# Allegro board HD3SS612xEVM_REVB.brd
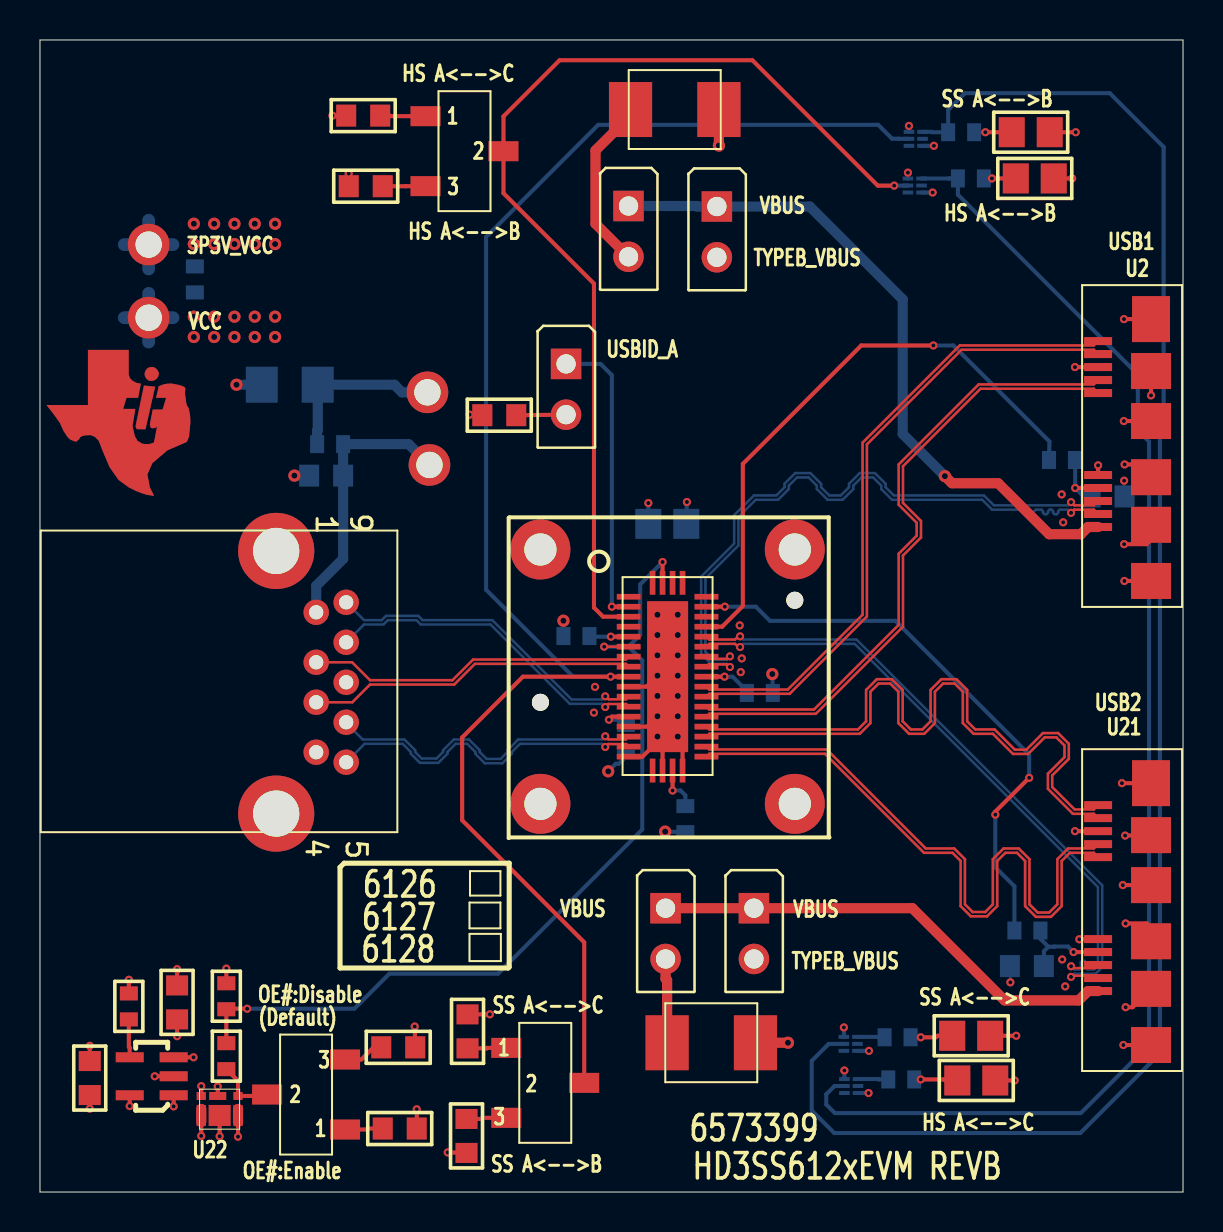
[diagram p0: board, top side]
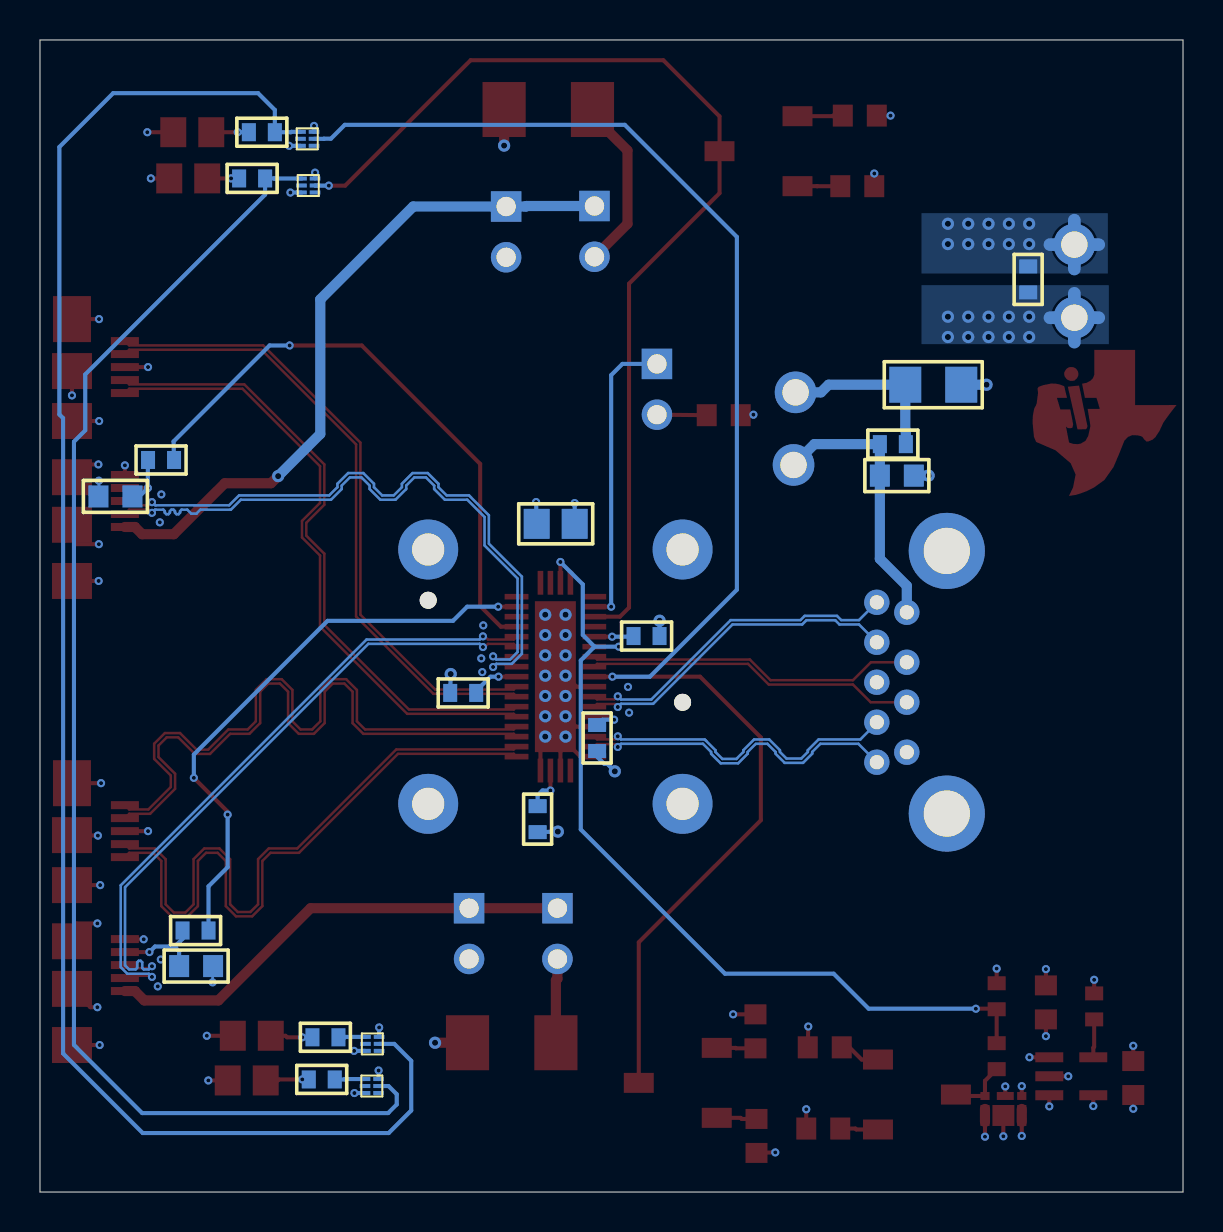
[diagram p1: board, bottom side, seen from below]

Outline 57.18 x 57.63 mm; copper layers: TOP, L2, L3, BOTTOM. Coordinates in mm from the lower left corner of the outline.
Outline path: 0,57.63 0,0 57.18,0 57.18,57.63 0,57.63

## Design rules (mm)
net group DIFFPAIR0: nets DEV_SSA_RX(N) DEV_SSA_RX(P)
net group DIFFPAIR1: nets DEV_HSA_DM DEV_HSA_DP
net group DIFFPAIR2: nets DEV_SSA_TX(N) DEV_SSA_TX(P)
net group DIFFPAIR3: nets USB1_DEV_SSB_RX(N) USB1_DEV_SSB_RX(P)
net group DIFFPAIR4: nets USB1_DEV_SSB_TX(N) USB1_DEV_SSB_TX(P)
net group DIFFPAIR5: nets USB1_HSB_DM USB1_HSB_DP
net group DIFFPAIR6: nets USB2_DEV_SSC_RX(N) USB2_DEV_SSC_RX(P)
net group DIFFPAIR7: nets USB2_DEV_SSC_TX(N) USB2_DEV_SSC_TX(P)
net group DIFFPAIR8: nets USB2_HSC_DM USB2_HSC_DP

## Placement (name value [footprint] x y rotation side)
C1  0.1uF  [0402]  29.31 23.36 270 bottom
C2  0.1uF  [0402]  27.48 27.81 180 bottom
C3  0.1uF  [0402]  32.28 19.3 270 bottom
C4  0.1uF  [0402]  35.36 24.97 0 bottom
C8  NC, 10uF  [0805]  30.43 33.43 0 bottom
C100  NC,100u  [0603]  15.16 35.84 180 bottom
C182  0.01uF  [0402]  4.45 8.64 90 top
C188  1uF  [0603]  6.86 8.64 90 top
C189  1uF  [0603]  2.49 4.85 90 top
D1  SCHOTTKY  [DO-214AA]  31.75 54.15 180 top
D5  SCHOTTKY  [DO-214AA]  33.58 7.47 180 top
D6  LED RED 0805  [0805]  48.61 53.02 0 top
D7  LED RED 0805  [0805]  45.63 7.82 0 top
D8  LED Orange 0805  [0805]  48.81 50.71 0 top
D9  LED Orange 0805  [0805]  45.89 5.58 0 top
F1  Fuse  [1206]  13.89 40.39 180 bottom
J1  CON02  [BERG1X2]  31.29 14.2 0 top
J2  CON02  [BERG1X2]  35.71 14.2 0 top
J3  CON02  [BERG1X2]  29.44 49.33 0 top
J4  CON02  [BERG1X2]  33.86 49.3 0 top
J5  CON02  [BERG1X2]  26.31 41.43 0 top
LP1  LP  [TESTLOOP]  5.44 47.4 0 top
LP2  LP  [TESTLOOP]  5.44 43.74 0 top
LP3  LP  [TESTLOOP]  19.48 36.37 0 top
LP4  LP  [TESTLOOP]  19.38 40.01 0 top
NOREF  -  []  3.54 0 90 top
NOREF#2  -  []  0 2 0 top
NOREF#3  -  []  4.01 39.17 0 top
R1  0R  [0402]  7.75 46.3 270 bottom
R2  4.98 K  [0603]  21.34 1.96 90 top
R3  4.98 K  [0603]  21.39 7.19 90 top
R6  4.98 K  [0603]  18.77 7.24 180 top
R7  4.98 K  [0603]  17.15 3.18 0 top
R18  100K  [0402]  9.32 9.14 90 top
R19  50K  [0402]  9.32 6.15 90 top
R20  0R  [0402]  15.16 37.41 180 bottom
R101  350  [0402]  46.73 53.02 180 bottom
R102  350  [0402]  43.55 7.74 180 bottom
R103  350  [0402]  45.91 50.71 0 bottom
R104  350  [0402]  42.43 5.63 0 bottom
R105  4.98 K  [0603]  15.44 50.32 0 top
R106  4.98 K  [0603]  17.02 53.85 180 top
R109  4.98 K  [0603]  23.83 38.86 180 top
R110  0R  [0402]  50.47 36.62 0 bottom
R111  NC, 4.98 K  [0603]  52.55 34.8 0 bottom
R112  0R  [0402]  48.74 13.08 0 bottom
R113  NC, 4.98 K  [0603]  50.22 11.3 180 bottom
SW1  Switch CJS-1201  [CJS-1200B]  13.31 4.88 180 top
SW2  Switch CJS-1201  [CJS-1200B]  25.27 5.46 0 top
SW3  Switch CJS-1201  [CJS-1200B]  21.23 52.07 0 top
U1  HD3SS612x Mux switch  [IRONWOOD_42PIN_C9856]  31.39 25.78 270 top
U2  USB3.0 Micro-B Receptacle  [USB3_MICRO_B_RECEPTACLE]  52.93 34.57 90 top
U20  USB3_STANDARD_TYPE_A_RECEPTACLE  [USB3_TYPEA]  15.32 25.5 270 top
U21  USB3.0 Micro-B Receptacle  [USB3_MICRO_B_RECEPTACLE]  52.93 11.35 90 top
U22  PMOS_PowerSwitch  [CSD25302Q2]  9.91 6.05 90 top
U23  SN74LVC1G04DSF  [DSF]  43.81 52.69 0 bottom
U24  SN74LVC1G04DSF  [DSF]  40.55 7.41 0 bottom
U25  LP3985IM5-3.3  [DBV_R-PDSO-G5]  5.59 5.79 180 top
U26  SN74LVC1G04DSF  [DSF]  43.76 50.35 0 bottom
U27  SN74LVC1G04DSF  [DSF]  40.58 5.3 0 bottom

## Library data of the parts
C1-C4 C8 = CAP
C100 = PCap_CaseD
C182 C188 C189 = CAP NP
D1 D5 = SCHOTTKY
D6-D9 = DIODE
F1 = Fuse_0
J1-J5 = CON02
LP1-LP4 = TESTLOOP
R1 R20 R110 R112 = R
R2 R3 R6 R7 R105 R106 R109 R111 R113 = r0603
R18 R19 = RES
R101-R104 = R_4
SW1-SW3 = Switch CJS-1201
U1 = HD3SS6126 Mux switch_11
U2 = USB3_1.0 Micro-B Receptacle
U20 = TMP_0
U21 = USB3_2.0 Micro-B Receptacle
U22 = PMOS_PowerSwitch_3
U23 U24 U26 U27 = SN74LVC1G04DSF
U25 = LP3985IM5-3_0.3

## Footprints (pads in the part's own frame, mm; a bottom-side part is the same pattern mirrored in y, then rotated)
0402
  rect 0.7x0.9 smd: 1(0,0) 2(1.3,0)
0603
  rect 1x1.1 smd: 1(0,0) 2(1.7,0)
0805
  rect 1.3x1.5 smd: 1(0,0) 2(1.9,0)
1206
  rect 1.6x1.8 smd: 1(0,0) 2(2.8,0)
BERG1X2
  rect 1.524x1.524 hole 0.965: 1(0,0)
  round 1.524 hole 0.965: 2(0,-2.54)
CJS-1200B
  rect 1.5x1 smd: 1(-1.95,1.75) 2(1.95,0) 3(-1.95,-1.75)
CSD25302Q2
  rect 0.4x0.46 smd: 1(-2.54,0) 2(-1.89,0) 3(-1.24,0) 4(-1.24,1.84) 5(-1.89,1.84) 6(-2.54,1.84)
  rect 0.4x0.85 smd: 7(-1.24,1.015)
  rect 1.05x1.1 smd: 8(-2.215,0.92)
DBV_R-PDSO-G5
  rect 1.4x0.5 smd: 1(-1.1,0.95) 2(-1.1,0) 3(-1.1,-0.95) 4(1.1,-0.95) 5(1.1,0.95)
DO-214AA
  rect 2.16x2.75 smd: 1(-2.21,0) 2(2.21,0)
DSF
  rect 0.53x0.2 smd: 1(-0.34,0.35) 2(-0.34,0) 3(-0.34,-0.35) 4(0.34,-0.35) 5(0.34,0) 6(0.34,0.35)
IRONWOOD_42PIN_C9856
  round 3 hole 1.61 unplated: (-6.362,6.362) (-6.362,-6.362) (6.362,6.362) (6.362,-6.362)
  round 0.85 hole 0.85 unplated: (-3.822,6.362) (1.282,-6.362)
  rect 0.28x1.19 smd: 1(-4,-1.947) 2(-3.5,-1.947) 3(-3,-1.947) 4(-2.5,-1.947) 5(-2,-1.947) 6(-1.5,-1.947) 7(-1,-1.947) 8(-0.5,-1.947) 9(0,-1.947) 10(0.5,-1.947) 11(1,-1.947) 12(1.5,-1.947) 13(2,-1.947) 14(2.5,-1.947) 15(3,-1.947) 16(3.5,-1.947) 17(4,-1.947) 22(4,1.943) 23(3.5,1.943) 24(3,1.943) 25(2.5,1.943) 26(2,1.943) 27(1.5,1.943) 28(1,1.943) 29(0.5,1.943) 30(0,1.943) 31(-0.5,1.943) 32(-1,1.943) 33(-1.5,1.943) 34(-2,1.943) 35(-2.5,1.943) 36(-3,1.943) 37(-3.5,1.943) 38(-4,1.943)
  rect 1.19x0.28 smd: 18(4.696,-0.752) 19(4.696,-0.252) 20(4.696,0.248) 21(4.696,0.748) 39(-4.696,0.748) 40(-4.696,0.248) 41(-4.696,-0.252) 42(-4.696,-0.752)
  rect 7.55x2.05 smd: 43(0,0)
TESTLOOP
  round 2.083 hole 1.321: 1(0,0)
USB3_MICRO_B_RECEPTACLE
  rect 0.4x1.4 smd: 1(-1.3,0) 2(-0.65,0) 3(0,0) 4(0.65,0) 5(1.3,0) 6(5.4,0) 7(6.05,0) 8(6.7,0) 9(7.35,0) 10(8,0)
  rect 1.8x2 smd: 11(-4,-2.648) 12(-1.19,-2.648) 13(1.19,-2.648) 14(4,-2.648) 15(6.5,-2.648)
  rect 2.3x1.9 smd: 16(9.1,-2.648)
USB3_TYPEA
  round 1.27 hole 0.711: 1(-3.5,-1.5) 2(-1,-1.5) 3(1,-1.5) 4(3.5,-1.5) 5(4,0) 6(2,0) 7(0,0) 8(-2,0) 9(-4,0)
  round 3.81 hole 2.311: 10(-6.57,-3.5) 11(6.57,-3.5)

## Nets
GND: C1.2(B) C2.2(B) C3.2(B) C4.2(B) C8.2(B) C100.2 C182.2 C188.2 C189.2 D6.2(K) D7.2(K) D8.2(K) D9.2(K) R3.2 R7.2 R18.2(B) R106.2 R109.2 R111.2 R113.2 U1.10(GND#10) U1.14(GND#14) U1.17(GND#17) U1.19(GND#19) U1.21(GND#21) U1.43(PAD) U2.5(GND) U2.8(GND_DRAIN) U2.11(SHIELD) U2.12(SHIELD1) U2.13(SHIELD2) U2.14(SHIELD3) U2.15(SHIELD4) U2.16(SHIELD5) U20.4(GND) U20.7(GND1) U20.10(SHIELD_GND1) U20.11(SHIELD_GND2) U21.5(GND) U21.8(GND_DRAIN) U21.11(SHIELD) U21.12(SHIELD1) U21.13(SHIELD2) U21.14(SHIELD3) U21.15(SHIELD4) U21.16(SHIELD5) U23.3(GND) U24.3(GND) U25.2(GND) U26.3(GND) U27.3(GND)
VBUS: C188.1 F1.2 U22.4(D1) U22.7(D2) U25.1(VIN) U25.3(VEN)
3P3V_VCC: C189.1 LP1.1 R1.1 R2.1 R105.1 U23.6(VDD) U24.6(VDD) U25.5(VOUT) U26.6(VDD) U27.6(VDD)
DEV_HSA_DM: U1.7(HSA(N)) U20.2(USB2_D_N)
DEV_HSA_DP: U1.8(HSA(P)) U20.3(USB2_D_P)
DEV_SSA_RX(N): U1.16(SSA1(N)) U20.5(USB3_RX_N)
DEV_SSA_RX(P): U1.15(SSA1(P)) U20.6(USB3_RX_P)
DEV_SSA_TX(N): U1.12(SSA0(N)) U20.8(USB3_TX_N)
DEV_SSA_TX(P): U1.11(SSA0(P)) U20.9(USB3_TX_P)
HS_SEL: SW3.2 U1.3(SEL1) U26.2(A)
OE#: R18.1(A) R19.2(B) U1.6(HS_OE0#) U1.41(HS_OE1#)
SS_SEL: SW2.2 U1.9(SEL0) U23.2(A)
TYPEB_VBUS: D1.1(K) D5.1(K) J2.2(P2) J4.2(P2) R6.1 U22.1(S1) U22.2(S2) U22.5(S3) U22.6(S4) U22.8(S5)
USB1_DEV_SSB_RX(N): U1.28(SSB0(N)) U2.9(MICB_SSRX-)
USB1_DEV_SSB_RX(P): U1.29(SSB0(P)) U2.10(MICB_SSRX+)
USB1_DEV_SSB_TX(N): U1.26(SSB1(N)) U2.6(MICB_SSTX-)
USB1_DEV_SSB_TX(P): U1.27(SSB1(P)) U2.7(MICB_SSTX+)
USB1_HSB_DM: U1.32(HSB0(N)) U2.2(D-)
USB1_HSB_DP: U1.31(HSB0(P)) U2.3(D+)
USB1_ID: R110.1 U1.35(HSB1(P))
USB1_MICB_ID: R110.2 R111.1 U2.4(ID)
USB2_DEV_SSC_RX(N): U1.24(SSC0(N)) U21.9(MICB_SSRX-)
USB2_DEV_SSC_RX(P): U1.25(SSC0(P)) U21.10(MICB_SSRX+)
USB2_DEV_SSC_TX(N): U1.22(SSC1(N)) U21.6(MICB_SSTX-)
USB2_DEV_SSC_TX(P): U1.23(SSC1(P)) U21.7(MICB_SSTX+)
USB2_HSC_DM: U1.34(HSC0(N)) U21.2(D-)
USB2_HSC_DP: U1.33(HSC0(P)) U21.3(D+)
USB2_ID: R112.1 U1.37(HSC1(P))
USB2_MICB_ID: R112.2 R113.1 U21.4(ID)
USBID_A: J5.1(P1) U1.2(HSA1(P))
N16697677: C1.1(A) C2.1(A) C3.1(A) C4.1(A) C8.1(A) LP2.1 R1.2 U1.5(VDD#5) U1.13(VDD#13) U1.20(VDD#20) U1.30(VDD#30)
N16756461: J1.1(P1) J2.1(P1) U21.1(VBUS)
N16757635: R19.1(A) SW1.2 U22.3(G)
N16757641: R7.1 SW1.1
N16757645: R6.2 SW1.3
N16758482: R2.2 SW2.3
N16758486: R3.1 SW2.1
N16761498: D7.1(A) R102.1
N16761564: D6.1(A) R101.1
N16761768: R101.2 U23.4(Y) U24.2(A)
N16762868: R102.2 U24.4(Y)
N16774048: C182.1 U25.4(BYPASS)
N16774634: C100.1 LP3.1 R20.1 U20.1(VBUS_PWR)
N16774662: F1.1 LP4.1 R20.2
N16778774: D5.2(A) J1.2(P2)
N16778838: J3.1(P1) J4.1(P1) U2.1(VBUS)
N16778841: D1.2(A) J3.2(P2)
N16779573: R105.2 SW3.3
N16779575: R106.1 SW3.1
N16780231: R103.1 U26.4(Y) U27.2(A)
N16780380: R104.1 U27.4(Y)
N16785274: J5.2(P2) R109.1
N167791880: D8.1(A) R103.2
N167792260: D9.1(A) R104.2

Pads without a net: U1 1 4 18 36 38 39 40 42; U23 1 5; U24 1 5; U26 1 5; U27 1 5

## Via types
v1: diameter 0.406, hole 0.203, TOP to BOTTOM, 95 vias
v2: diameter 0.61, hole 0.305, TOP to BOTTOM, 43 vias

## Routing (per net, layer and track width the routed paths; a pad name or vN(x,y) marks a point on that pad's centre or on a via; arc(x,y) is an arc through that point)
GND: length 75.3
  TOP w0.203: C188.2 v1(6.86,11.15) ; v2(31.9,22.78) 31.9,22.29 32.14,22.05 U1.21 ; U21.5 v1(51.99,12.64) ; U1.19 31.14,22.03 30.89,22.29 v2(30.89,22.78) 30.54,22.43 30.54,22.18 30.14,21.78 U1.17 ; U2.12 55.58,32.63 55.36,32.41 v1(54.23,32.41) ; U21.12 54.66,9.25 v1(54.31,9.25) ; R109.2 22.1,38.89 v1(21.49,38.89) ; U2.15 v1(55.58,39.85) ; v2(30.89,23.8) 30.37,23.28 U1.14 ; v1(18.85,4.14) 18.85,3.18 R7.2 ; U2.8 v1(51.77,41.27) ; U21.13 55.58,13.22 55.36,13.44 v1(54.31,13.44) ; U2.14 v1(54.22,38.57) ; v1(48.76,5.58) D9.2 ; U2.13 55.58,36.18 55.36,36.4 v1(54.25,36.4) ; U2.11 v1(54.24,30.57) ; U21.11 v1(54.19,7.35) ; R106.2 v1(14.63,53.85) ; U2.16 v1(54.22,43.67) ; v2(30.89,25.83) 30.34,25.28 U1.10 ; U21.15 v1(54.28,17.83) ; C189.2 v1(2.49,7.32) ; U21.14 v1(54.16,15.35) ; D6.2 v1(51.81,53.02) ; v1(22.5,8.89) 21.39,8.89 R3.2 ; U21.16 v1(54.12,20.45) ; C182.2 v1(4.45,10.62) ; R18.2 v1(9.32,11.18) ; U2.5 v1(52.93,36.35) ; U25.2 v1(5.74,5.79) ; D8.2 v1(51.63,50.71) ; U21.8 v1(51.77,18.05) ; v1(48.83,7.82) D7.2
  L2 w0.127: 15.32,24.69 U20.7 ; U20.7 16.13,25.5 ; U20.7 15.32,26.31 ; U20.7 14.5,25.5 ; 11.82,29.99 U20.10 ; U20.10 13.9,32.07 ; U20.10 11.82,34.15 ; U20.10 9.73,32.07 ; U20.11 13.9,18.93 ; U20.11 11.82,16.85 ; U20.11 11.82,21.01 ; U20.11 9.73,18.93 ; 13.82,21.19 U20.4 ; U20.4 14.63,22 ; U20.4 13,22 ; U20.4 13.82,22.81
  BOTTOM w0.127: v1(54.23,35.59) 54.23,34.82 R111.2 ; R113.2 48.54,11.28 v1(48.54,10.49)
  BOTTOM w0.203: v2(28.42,21.05) 28.8,21.42 28.95,21.42 29.31,21.78 C1.2 ; C3.2 v2(31.27,18.03) ; U23.3 v1(43.47,53.33) ; U27.3 v1(40.24,6.08) ; U26.3 v1(43.42,51) ; C4.2 v2(36.63,25.91) ; U24.3 v1(40.21,8.23) ; C2.2 v2(26.18,28.58) ; C8.2 v1(32.36,34.52)
  BOTTOM w0.508: C100.2 v2(12.73,35.84)
  vias: v1(27.71,23.98) v1(27.76,25.27) v1(35,28.35) v1(35.05,26.01) v1(35.1,26.7) v1(51.1,34.9) v1(51.13,11.63) v1(51.18,33.5) v1(51.28,10.29) v2(30.89,28.88) v2(30.89,27.86) v2(30.89,26.85) v2(30.89,24.82) v2(31.9,28.88) v2(31.9,27.86) v2(31.9,26.85) v2(31.9,25.83) v2(31.9,24.82) v2(31.9,23.8)
VBUS: length 4.6
  TOP w0.203: U22.7 v1(8.89,5.28) ; U22.4 v1(8.07,5.3) ; U25.1 v1(6.69,4.28) ; C188.1 v1(6.86,7.8) ; U25.3 v1(7.68,6.74)
  BOTTOM w0.508: F1.2 v2(9.83,40.39)
3P3V_VCC: length 13.6
  TOP w0.203: R105.1 v1(15.44,50.95) ; U25.5 v1(4.49,4.3) ; R2.1 v1(20.4,1.98) ; C189.1 v1(2.49,4.17)
  L3 w0.635: LP1.1 6.65,47.4 ; LP1.1 5.44,48.62 ; LP1.1 4.22,47.4
  BOTTOM w0.203: U24.6 v1(41.47,7.06) ; U26.6 v1(44.65,50) ; U27.6 v1(41.45,4.95) ; U23.6 v1(44.72,52.34)
  BOTTOM w0.635: 4.22,47.4 LP1.1 ; LP1.1 5.44,48.62 ; LP1.1 6.65,47.4 ; LP1.1 5.44,46.18
  vias: v2(7.7,48.44) v2(7.7,47.42) v2(8.71,48.44) v2(8.71,47.42) v2(9.73,48.44) v2(9.73,47.42) v2(10.74,48.44) v2(10.74,47.42) v2(11.76,48.44) v2(11.76,47.42)
DEV_HSA_DM: length 16.5
  TOP w0.127: U1.7 29.31,26.64 21.67,26.64 20.63,25.6 16.51,25.6 15.61,26.5 U20.2
DEV_HSA_DP: length 16.5
  TOP w0.127: U1.8 29.31,26.42 21.76,26.42 20.72,25.39 16.51,25.39 15.62,24.5 U20.3
DEV_SSA_RX(N): length 16.5
  TOP w0.127: U1.16 29.32,22.41 28.42,22.41 v1(28.27,22.26)
  BOTTOM w0.127: U20.5 16.24,22.42 18.14,22.42 18.55,22.01 18.55,21.92 19.01,21.47 19.92,21.47 20.38,21.92 20.38,22.01 20.79,22.42 21.37,22.42 21.78,22.01 21.78,21.92 22.25,21.45 23.13,21.45 23.6,21.92 23.6,22.01 24.01,22.42 28.12,22.42 v1(28.27,22.26)
DEV_SSA_RX(P): length 16.5
  TOP w0.127: v1(28.27,22.8) 28.43,22.64 29.31,22.64 U1.15
  BOTTOM w0.127: v1(28.27,22.8) 28.12,22.64 23.92,22.64 23.86,22.58 23.39,22.1 23.39,22.01 23.04,21.67 22.34,21.67 21.99,22.01 21.99,22.1 21.46,22.64 20.7,22.64 20.16,22.1 20.16,22.01 19.83,21.69 19.09,21.69 18.77,22.01 18.77,22.1 18.23,22.64 16.14,22.64 15.32,23.46 U20.6
DEV_SSA_TX(N): length 16.5
  TOP w0.127: U1.12 29.31,24.42 28.42,24.42 v1(28.27,24.26)
  BOTTOM w0.127: U20.8 16.21,28.39 17.18,28.39 17.4,28.61 18.83,28.61 19.05,28.39 22.53,28.39 26.51,24.42 28.12,24.42 v1(28.27,24.26)
DEV_SSA_TX(P): length 16.5
  TOP w0.127: v1(28.27,24.8) 28.3,24.8 28.45,24.65 29.31,24.65 U1.11
  BOTTOM w0.127: v1(28.27,24.8) 28.12,24.64 26.59,24.64 22.62,28.61 19.14,28.61 18.92,28.82 17.31,28.82 17.1,28.61 16.21,28.61 U20.9
HS_SEL: length 52.4
  TOP w0.203: U1.3 28.17,28.78 27.71,29.24 27.71,45.44 23.18,49.97 SW3.2 23.18,53.81 25.99,56.62 35.63,56.62 41.91,50.35 v1(42.73,50.35)
  BOTTOM w0.203: v1(42.73,50.35) 43.41,50.35 U26.2
OE#: length 44.1
  TOP w0.127: U1.6 v1(28.22,27.28)
  TOP w0.203: v1(10.36,9.17) 9.35,9.17 R18.1 R19.2 ; U1.41 v1(31.14,31.52)
  BOTTOM w0.203: v1(10.36,9.17) 15.72,9.17 17.48,10.92 22.91,10.92 30.13,18.14 30.13,26.59 29.44,27.28 ; v1(31.14,31.52) 30.02,30.4 30.02,27.87 29.44,27.28 ; 29.44,27.28 v1(28.22,27.28)
SS_SEL: length 78.8
  TOP w0.203: SW2.2 27.22,12.49 21.12,18.6 21.12,22.74 24.16,25.78 v1(28.54,25.78) U1.9
  BOTTOM w0.203: v1(28.54,25.78) 26.66,25.78 22.32,30.13 22.32,47.78 27.92,53.39 41.93,53.39 42.62,52.7 42.97,52.7 42.97,52.69 U23.2
TYPEB_VBUS: length 15.3
  TOP w0.203: R6.1 v1(18.75,8.28) ; U22.8 v1(8.99,2.79) ; U22.6 v1(8.07,2.81) ; U22.1 v1(9.91,2.77)
  TOP w0.508: D1.1 v2(33.96,52.35) ; U22.2 U22.1 ; U22.5 U22.6 ; D5.1 v2(37.41,7.47)
  L3 w0.635: 35.71,10.78 J2.2 ; J2.2 36.59,11.66 ; J2.2 34.84,11.66 ; J2.2 35.71,12.53 ; J4.2 34.73,46.76 ; J4.2 33.86,47.64 ; J4.2 33.86,45.89 ; J4.2 32.98,46.76
USB1_DEV_SSB_RX(N): length 31.9
  TOP w0.127: U1.28 33.48,24.92 37.5,24.92 41.36,28.79 41.36,37.4 46.1,42.14 52.71,42.14 U2.9
USB1_DEV_SSB_RX(P): length 31.9
  TOP w0.127: U1.29 33.48,25.14 37.41,25.14 41.15,28.88 41.15,37.49 46.01,42.35 52.71,42.35 52.93,42.57 U2.10
USB1_DEV_SSB_TX(N): length 31.9
  TOP w0.127: U2.6 52.71,40.19 47.05,40.19 43.17,36.31 43.17,34.47 44.07,33.57 44.07,32.74 43.17,31.84 43.17,28.28 38.81,23.92 33.48,23.92 U1.26
USB1_DEV_SSB_TX(P): length 31.9
  TOP w0.127: U1.27 33.48,24.14 38.72,24.14 42.95,28.37 42.95,31.93 43.85,32.83 43.85,33.48 42.95,34.38 42.95,36.4 46.96,40.4 52.71,40.4 52.93,40.62 U2.7
USB1_HSB_DM: length 31.9
  TOP w0.127: U1.32 33.45,26.67 34.38,26.67 v1(34.51,26.8) ; U2.2 52.71,34.14 51.73,34.14 v1(51.57,33.98)
  BOTTOM w0.127: v1(51.57,33.98) 51.42,34.14 51.01,34.14 50.93,34.06 50.93,33.98 50.86,33.91 50.75,33.91 50.68,33.98 50.68,34.06 50.6,34.14 50.5,34.14 50.42,34.06 50.42,33.98 50.35,33.91 50.24,33.91 50.17,33.98 50.17,34.06 50.09,34.14 49.81,34.14 49.61,33.93 49.35,33.93 49.15,34.14 47.63,34.14 47.13,34.63 42.62,34.63 42.08,35.17 42.08,35.34 41.67,35.75 41.09,35.75 40.68,35.34 40.68,35.17 40.15,34.63 39.39,34.63 38.86,35.17 38.86,35.34 38.45,35.75 37.87,35.75 37.46,35.34 37.46,35.17 36.92,34.63 35.8,34.63 34.94,33.77 34.94,32.35 33.29,30.7 33.29,27.01 33.66,26.64 34.35,26.64 v1(34.51,26.8)
USB1_HSB_DP: length 31.9
  TOP w0.127: U2.3 52.93,34.57 52.71,34.35 51.73,34.35 v1(51.57,34.51) ; U1.31 33.45,26.39 34.36,26.39 34.49,26.26 v1(34.51,26.26)
  BOTTOM w0.127: v1(34.51,26.26) 34.35,26.42 33.57,26.42 33.07,26.92 33.07,30.78 34.72,32.44 34.72,33.86 35.71,34.85 36.83,34.85 37.24,35.26 37.24,35.43 37.78,35.97 38.54,35.97 39.07,35.43 39.07,35.26 39.48,34.85 40.06,34.85 40.47,35.26 40.47,35.43 41,35.97 41.76,35.97 42.3,35.43 42.3,35.26 42.71,34.85 47.22,34.85 47.71,34.35 51.42,34.35 v1(51.57,34.51)
USB1_ID: length 30.1
  TOP w0.203: U1.35 34.12,28.28 35.16,29.32 35.16,36.43 41.08,42.35 v1(44.69,42.35)
  BOTTOM w0.203: R110.1 50.5,37.54 45.69,42.35 v1(44.69,42.35)
USB1_MICB_ID: length 3.5
  TOP w0.203: U2.4 v1(51.78,35.22)
  BOTTOM w0.203: R110.2 51.78,36.21 v1(51.78,35.22) 52.2,34.8 R111.1
USB2_DEV_SSC_RX(N): length 32.4
  TOP w0.127: U1.24 33.48,22.92 41,22.92 41.54,23.46 41.54,25.03 41.95,25.44 42.53,25.44 42.94,25.03 42.94,23.46 43.47,22.92 44.23,22.92 44.76,23.46 44.76,25.03 45.17,25.44 45.75,25.44 46.16,25.03 46.16,23.46 46.7,22.92 47.66,22.92 48.67,21.91 49.43,21.91 50.26,22.75 50.84,22.75 51.25,22.34 51.25,21.76 50.42,20.93 50.42,20.17 51.67,18.92 52.71,18.92 U21.9
USB2_DEV_SSC_RX(P): length 32.4
  TOP w0.127: U1.25 33.48,23.14 40.91,23.14 41.32,23.55 41.32,25.12 41.86,25.65 42.62,25.65 43.15,25.12 43.15,23.55 43.56,23.14 44.14,23.14 44.55,23.55 44.55,25.12 45.08,25.65 45.84,25.65 46.38,25.12 46.38,23.55 46.79,23.14 47.75,23.14 48.76,22.13 49.34,22.13 50.17,22.96 50.93,22.96 51.46,22.43 51.46,21.67 50.63,20.84 50.63,20.26 51.76,19.14 52.71,19.14 52.93,19.35 U21.10
USB2_DEV_SSC_TX(N): length 32.4
  TOP w0.127: U1.22 33.48,21.92 39.27,21.92 44.22,16.97 45.64,16.97 46.05,16.56 46.05,14.3 46.56,13.79 47.37,13.79 47.88,14.3 47.88,16.56 48.29,16.97 48.87,16.97 49.28,16.56 49.28,14.3 49.81,13.77 50.57,13.77 51.11,14.3 51.11,16.56 51.52,16.97 52.71,16.97 52.93,16.76 U21.6
USB2_DEV_SSC_TX(P): length 32.4
  TOP w0.127: U21.7 52.93,17.4 52.71,17.19 51.43,17.19 50.89,16.65 50.89,14.39 50.48,13.98 49.9,13.98 49.49,14.39 49.49,16.65 48.96,17.19 48.2,17.19 47.66,16.65 47.66,14.39 47.28,14.01 46.65,14.01 46.27,14.39 46.27,16.65 45.73,17.19 44.31,17.19 39.35,22.14 33.48,22.14 U1.23
USB2_HSC_DM: length 32.4
  TOP w0.127: v1(35.02,27.8) 34.93,27.8 34.77,27.64 33.48,27.64 U1.34 ; v1(51.57,10.76) 51.63,10.82 52.81,10.82 U21.2
  BOTTOM w0.127: v1(51.57,10.76) 51.73,10.92 52.81,10.92 53.14,11.25 53.14,15.34 40.84,27.64 35.18,27.64 v1(35.02,27.8)
USB2_HSC_DP: length 32.4
  TOP w0.127: U21.3 52.78,11.2 51.67,11.2 v1(51.57,11.3) ; U1.33 33.48,27.42 34.77,27.42 34.93,27.26 v1(35.02,27.26)
  BOTTOM w0.127: v1(51.57,11.3) 51.73,11.14 51.99,11.14 52.06,11.21 52.06,11.49 52.14,11.57 52.24,11.57 52.32,11.49 52.32,11.21 52.39,11.14 52.72,11.14 52.92,11.34 52.92,15.25 40.75,27.42 35.18,27.42 v1(35.02,27.26)
USB2_ID: length 29.1
  TOP w0.203: U1.37 v1(34.26,29.28) ; v1(47.79,18.88) 47.79,19.03 v1(49.48,20.72)
  BOTTOM w0.203: v1(34.26,29.28) 35.81,29.28 36.52,28.57 42.79,28.57 49.48,21.89 v1(49.48,20.72) ; v1(47.79,18.88) 47.79,16.25 48.74,15.3 R112.1
USB2_MICB_ID: length 4.6
  TOP w0.203: U21.4 v1(51.7,12)
  BOTTOM w0.203: R112.2 50.04,12.67 50.44,12.27 ; 50.44,12.27 50.72,12.27 50.74,12.28 51.42,12.28 v1(51.7,12) ; 50.44,12.27 50.22,12.04 R113.1
USBID_A: length 14.9
  TOP w0.203: U1.2 v1(28.61,29.28)
  BOTTOM w0.203: J5.1 28.04,41.43 28.61,40.86 v1(28.61,29.28)
N16697677: length 19.5
  TOP w0.203: U1.30 v1(34.24,25.78) ; v1(28.46,23.63) 28.61,23.78 U1.13 ; U1.20 v1(31.64,20.09) ; U1.5 v1(28.56,27.78)
  L3 w0.635: 5.44,42.52 LP2.1 ; LP2.1 6.65,43.74 ; LP2.1 4.22,43.74 ; LP2.1 5.44,44.96
  BOTTOM w0.203: C2.1 27.51,27.78 v1(28.56,27.78) ; v1(28.46,23.63) 29.04,23.63 C1.1 ; C4.1 35.36,25.07 34.64,25.78 v1(34.24,25.78) ; C3.1 32.28,19.84 32.04,20.09 v1(31.64,20.09) ; C8.1 v1(30.43,34.47)
  BOTTOM w0.635: LP2.1 5.44,44.96 ; LP2.1 6.65,43.74 ; LP2.1 5.44,42.52 ; LP2.1 4.22,43.74
  vias: v2(7.7,43.79) v2(7.7,42.77) v2(8.71,43.79) v2(8.71,42.77) v2(9.73,43.79) v2(9.73,42.77) v2(10.74,43.79) v2(10.74,42.77) v2(11.76,43.79) v2(11.76,42.77)
N16756461: length 23.7
  TOP w0.508: U21.1 52.43,10.05 51.96,9.58 48.25,9.58 43.64,14.2 J2.1 J1.1
N16757635: length 3.1
  TOP w0.203: SW1.2 11.29,4.81 U22.3 9.91,5.56 R19.1
N16757641: length 1.9
  TOP w0.203: R7.1 16.39,3.18 16.34,3.13 SW1.1
N16757645: length 2.1
  TOP w0.203: SW1.3 16.08,6.63 16.69,7.24 R6.2
N16758482: length 2
  TOP w0.203: R2.2 22.08,3.66 22.13,3.71 SW2.3
N16758486: length 1.9
  TOP w0.203: R3.1 22.36,7.19 22.38,7.21 SW2.1
N16761498: length 2.1
  TOP w0.203: D7.1 44.89,7.82 44.82,7.74 v1(44.06,7.74)
  BOTTOM w0.203: R102.1 v1(44.06,7.74)
N16761564: length 1.9
  TOP w0.203: v1(47.29,53.02) D6.1
  BOTTOM w0.203: R101.1 v1(47.29,53.02)
N16761768: length 84
  BOTTOM w0.203: U24.2 39.45,7.41 38.61,6.56 38.61,4.08 39.73,2.95 52.04,2.95 56.02,6.93 56.02,38.71 56.21,38.9 56.21,52.28 53.51,54.97 46.27,54.97 45.43,54.13 R101.2 44.62,53.02 44.6,53.04 U23.4
N16762868: length 1.4
  BOTTOM w0.203: R102.2 41.92,7.74 41.9,7.76 U24.4
N16774048: length 1.9
  TOP w0.203: U25.4 4.49,7.22 4.45,7.26 C182.1
N16774634: length 13.7
  BOTTOM w0.508: LP3.1 18.44,37.41 R20.1 C100.1 15.16,31.67 13.82,30.33 U20.1
N16774662: length 8.6
  BOTTOM w0.508: R20.2 13.86,38.09 13.89,38.12 F1.1 17.73,40.39 18.11,40.01 LP4.1
N16778774: length 4.2
  TOP w0.508: D5.2 31.37,10.59 31.29,10.67 J1.2
N16778838: length 34.4
  TOP w0.508: U2.1 52.43,33.27 52.07,32.91 50.48,32.91 47.93,35.46 45.62,35.46 v2(45.26,35.81)
  BOTTOM w0.508: J3.1 32.84,49.33 32.87,49.3 J4.1 38.51,49.3 43.15,44.65 43.15,37.92 v2(45.26,35.81)
N16778841: length 8.8
  TOP w0.508: J3.2 27.79,48.44 27.79,52.11 29.54,53.86 D1.2
N16779573: length 2.1
  TOP w0.203: SW3.3 18.31,50.32 18.3,50.32 R105.2
N16779575: length 2.3
  TOP w0.203: R106.1 17.5,53.85 17.53,53.82 SW3.1
N16780231: length 68.5
  BOTTOM w0.203: U26.4 45.46,50.7 45.47,50.71 R103.1 45.91,49.89 54.91,40.9 54.91,38.1 55.48,37.54 55.48,7.36 52.07,3.95 39.76,3.95 39.33,4.38 39.33,4.89 39.74,5.3 U27.2
N16780380: length 1.5
  BOTTOM w0.203: R104.1 41.95,5.63 41.93,5.65 U27.4
N16785274: length 2.5
  TOP w0.203: R109.1 J5.2
N167791880: length 1.6
  TOP w0.203: v1(47.62,50.71) D8.1
  BOTTOM w0.203: R103.2 v1(47.62,50.71)
N167792260: length 2.2
  TOP w0.203: D9.1 45.28,5.58 45.22,5.63 v1(44.06,5.63)
  BOTTOM w0.203: R104.2 v1(44.06,5.63)

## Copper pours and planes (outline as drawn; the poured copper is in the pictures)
GND on L2: 0.51,0.51 0.51,57.18 56.67,57.18 56.67,0.51
VBUS on L3: 11.94,41.33 11.94,36.25 6.2,30.51 6.2,8.99 7.98,7.21 10.06,7.21 10.19,7.09 10.19,5.28 8.85,3.95 6.41,3.95 4.75,5.52 4.75,38.56 7.59,41.4 11.86,41.4
3P3V_VCC on BOTTOM: 3.76,48.97 3.76,45.95 13.08,45.95 13.08,48.97
3P3V_VCC on L3: 0.51,0.51 0.51,57.05 56.67,57.05 56.67,0.51 ; 1 cut-out
Net_6 on TOP (solid shape): 4.44,40.89 4.51,40.7 4.63,40.58 4.84,40.48 5.05,40.44 4.91,39.73 4.33,39.73 4.16,39.18 4.77,39.18 4.63,38.32 4.74,37.83 4.87,37.58 5.12,37.44 5.27,37.41 5.49,37.43 5.52,37.43 5.7,37.5 5.85,38.29 5.76,38.22 5.64,38.21 5.53,38.23 5.49,38.4 5.64,39.15 6.13,39.15 6.31,39.73 5.8,39.73 5.94,40.31 6.17,40.4 6.38,40.44 6.59,40.45 7,40.36 7.22,40.28 7.28,40.2 7.25,39.98 7.32,39.45 7.36,39.34 7.44,39.19 7.51,38.83 7.53,38.5 7.46,37.78 7.35,37.52 6.38,37.11 5.62,36.46 5.37,35.9 5.5,35.25 5.71,34.82 5.35,34.88 5.09,34.96 4.83,35.06 4.44,35.25 3.93,35.62 3.47,36.27 3.14,37.06 2.94,37.58 2.76,37.77 2.54,37.86 2.28,37.85 2.1,37.81 2.03,37.77 1.95,37.65 1.82,37.54 1.71,37.56 1.51,37.64 1.38,37.77 1.18,38.07 0.99,38.49 0.68,38.92 0.33,39.37 0.74,39.37 2.4,39.37 2.4,42.13 4.44,42.13
Net_7 on TOP (solid shape): 5.76,40.29 5.35,38.47 5.28,38.15 4.85,38.16 4.8,38.23 4.78,38.32 5.2,40.34 5.2,40.35
TYPEB_VBUS on L3: 35.64,0.53 28.42,7.75 16.48,7.75 10.85,2.11 7.82,2.11 7.06,2.87 7.06,3.18 9.63,3.18 10.9,4.45 10.9,9.32 12.95,11.38 26.37,11.38 26.31,11.43 28.4,11.43 30.1,13.13 35.92,13.13 38.38,10.67 38.38,3.96 39.34,3 54.28,3 54.69,3.4 54.69,36.2 53.67,37.21 35.36,37.21 34.82,37.74 34.82,42.04 32.36,44.5 32.36,52.35 33.68,53.67 36.78,53.67 38.89,51.56 38.89,45.54 42.44,41.99 55.4,41.99 56.79,40.59 56.79,2.59 54.74,0.53
N16697677 on BOTTOM: 3.71,45.36 3.71,42.42 13.08,42.42 13.08,45.36
N16697677 on L3: 8.15,12.14 7.54,12.75 7.54,30.38 12.75,35.59 12.75,40.69 11.73,41.71 4.98,41.71 3.71,42.98 3.71,45.39 14.27,45.39 17.45,42.21 23.72,42.21 35.13,30.81 35.13,21.39 25.88,12.14

Small or netless copper shapes (teardrops, artwork), in the pictures only: 1 on TOP

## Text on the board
Ref Des/Silkscreen Top: 3P3V_VCC | VCC | OE#:Enable | OE#:Disable | (Default) | 2 | 1 | 3 | HS A<-->C | HS A<-->B | SS A<-->B | SS A<-->C | VBUS | USBID_A | TYPEB_VBUS | USB2 | USB1 | 6128 | 6127 | 6126 | 6573399 | HD3SS612xEVM REVB
PAGE_OUTLINE: GENERAL NOTES. UNLESS OTHERWISE SPECIFIED | 1.  ALL FABRICATION ITEMS MUST MEET OR EXCEED BEST | INDUSTRY PRACTICE : IPC-A-600C (Commercial std.) | 2.  LAMINATE MATERIAL  :  FR4 POLYCLAD 370 or EQUIVALENT | 3.  COPPER WEIGHT  : 1oz START INTERNAL, 1/2oz START EXTERNAL | 4.  FINISHED BOARD THICKNESS :  .060  +/- 10% | 5.  MAXIMUM WARP AND TWIST TO BE :  .005 INCH PER INCH | 6.  MINIMUM COPPER WALL THICKNESS OF PLATED-THRU | HOLES TO BE .001 INCH. THERE MUST BE 1MIL OR GREATER PLATING ON | EACH SIDE OF THE BARREL WHEN VIEWED IN THE CROSS SECTION | 7.  MINIMUM ANNULAR RING OF PLATED-THRU HOLES | TO BE .002 INCH | 8.  MAXIMUM ALLOWABLE LINE REDUCTION TO BE | 20% OR .002 WHICHEVER IS SMALLER | 9.  0.005 SIGNAL LINES ON LAYER 1 & 4 TO BE | IMPEDANCE CONTROLLED 100 OHMS DIFFERENTIAL +/- 5% | 10. 0.008 SIGNAL LINES ON LAYER 1 & 4 TO BE | IMPEDANCE CONTROLLED 50 OHMS +/- 5% | 11. DIELECTRIC CONSTANTS ARE         CORE : 4.1 | PREPREG : 4.1 | 13. A CROSS SECTION MOUNT AND DIGITAL PHOTO'S OF VIA'S TO BE PROVIDED | 14. USE THE (DRPP) DUTCH REVERSE PLATING PROCESS | PROCESS NOTES | 1. CIRCUITRY ON OUTER LAYERS TO BE PLATED WITH : NICKEL GOLD | 2. SOLDERMASK BOTH SIDES PER ARTWORK  :  GREEN LPI | 3. SILKSCREEN BOTH SIDES PER ARTWORK  :  COLOR = WHITE
DIMENSION: 45mil | 5mil | 1 | 2 | 3 | 4 | TOP | L2 | L3 | BOTTOM
COMPVAL_TYPE_TOP: FIGURE | SIZE | 91.0 | 52.0 | 38.0 | 28.0 | 12.0 | 8.0 | 63.39 | 33.461 | DRILL CHART: TOP to BOTTOM | ALL UNITS ARE IN MILS | TOLERANCE | +3.0/-3.0 | +0.0/-0.0 | +3.0/-12.0 | PLATED | NON-PLATED | QTY | 2 | 4 | 10 | 9 | 43 | 95
